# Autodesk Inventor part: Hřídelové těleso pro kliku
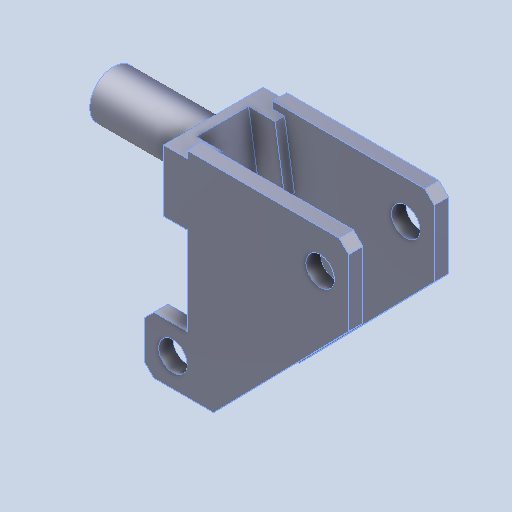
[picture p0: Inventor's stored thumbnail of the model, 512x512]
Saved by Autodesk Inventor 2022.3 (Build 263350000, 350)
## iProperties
Created: 2022-03
Part Number: Hřídelové těleso pro kliku
Material: Všeobecné
Document SubType Name: Modeling
Designer: Hra42
Density: 1 g/cm^3
Appearance: Výchozí
Author: Hra42
Sending System: SolidWorks 2012
Last Author: Hra42
Last Saved: 2025-11-13
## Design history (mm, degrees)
feature "Importovaný1"
node "Těleso1"
